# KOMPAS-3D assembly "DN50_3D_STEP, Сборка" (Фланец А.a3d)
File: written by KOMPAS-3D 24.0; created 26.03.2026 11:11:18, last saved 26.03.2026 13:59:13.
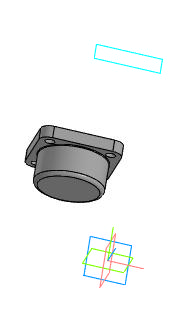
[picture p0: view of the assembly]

Document properties: Автор: R2D2; Полное имя файла: E:\Работа\Зайцев\GVWR2121M-2W-F-ОСТ Задвижка клиновая с видвижным штоком Ду50-300 Ру16\DN80\Исходные материалы\Фланец А.a3d

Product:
- Body: Тело 2  | qty 1
    Масса: 2.698751
- Part/product: DN50_3D_STEP  | designation Сборка
    Масса: 2.725126

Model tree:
1. Перпендикулярная плоскость:2
     Координата Z = -90
2. Операция без истории:2
3. Эскиз:1  (with: Грань.Операция без истории:2, Ребро.Операция без истории:2)
4. Элемент выдавливания:1  (with: Грань.Операция без истории:2)
     Расстояние 2 = 14.5
5. Массив по концентрической сетке:1  (with: Элемент выдавливания:1, Грань.Операция без истории:2)  (4 pattern instances)
     Шаг 2 = 360
6. Скругление:1
     Радиус = 13.5
7. Эскиз:2  (with: Грань.Операция без истории:2, Ребро.Операция без истории:2)
8. Элемент выдавливания:2
     Расстояние 2 = 20
9. Эскиз:3  (with: Грань.Операция без истории:2, Ребро.Операция без истории:2)
10. Элемент выдавливания:3  (with: Грань.Операция без истории:2)
     Расстояние 2 = 3
11. Эскиз:4  (with: Грань.Операция без истории:2, Ребро.Операция без истории:2)
12. Элемент выдавливания:4
     Расстояние 1 = 3
13. Скругление:2  (with: Ребро.Операция без истории:2)
     Радиус = 5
